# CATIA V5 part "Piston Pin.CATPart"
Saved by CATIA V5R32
Part number: Piston Pin
Bounding box of the stored display mesh (mm): x -11 to 11, y -10.833 to 10.833, z -40 to 40
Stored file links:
  D:\PROJECTS\Project 2022\CATIA V5 6R 2022\Resources\Part Files\c13_catia_v5_6r2022_prt\c13_catia_v5-6r2022_figr_13-41\Part & Asm files\Piston Pin.CATPart
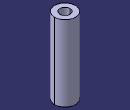
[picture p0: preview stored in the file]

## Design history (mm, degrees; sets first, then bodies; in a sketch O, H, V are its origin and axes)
Body1 (main body)
  Sketch1 on xy-plane, origin (0, 0, 0), H (1, 0, 0), V (0, 1, 0)
    circle A1 centre (0, 0) radius 5.5
    circle A2 centre (0, 0) radius 11
    point P1 (0, 0)
    radius A2 = 11
    radius A1 = 5.5
    coincidence: P1 H
    concentricity: A1 A2
  Pad1: profile Sketch1, direction (0, 0, 1), length 40, mirrored extent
